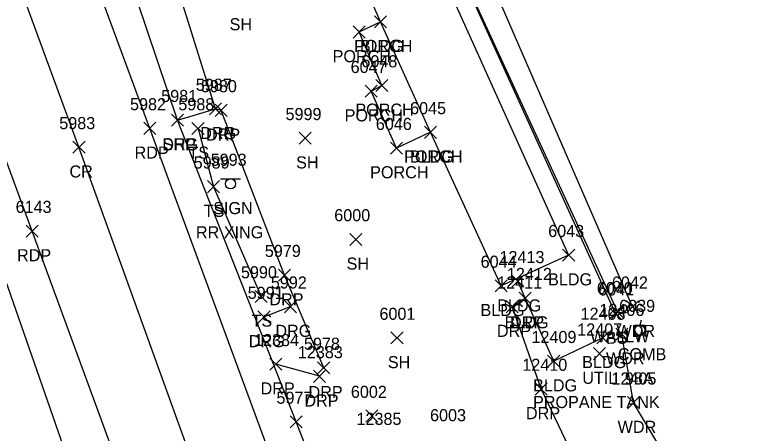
# Model space of a CAD drawing. Extents: x 1769141 to 1770817, y 735471 to 742405.
# Drawn here: x 1770316.5 to 1770439.6, y 740432.3 to 740501.5 of the extents above; entities that cross this region are included whole.
import ezdxf

# ---------------------------------------------------------------- set-up
doc = ezdxf.new("R2010")
doc.units = 0
for name, color, linetype in [('L_A', 7, 'Continuous'), ('L_I', 7, 'Continuous'), ('L_TIC', 7, 'Continuous'), ('LAWA', 7, 'Continuous'), ('LBC', 7, 'Continuous'), ('LBF', 7, 'Continuous'), ('LELB', 7, 'Continuous'), ('LW', 7, 'Continuous'), ('P_A', 7, 'Continuous'), ('P_I', 7, 'Continuous'), ('P_TIC', 7, 'Continuous'), ('PET', 7, 'Continuous'), ('PRC', 7, 'Continuous'), ('PSP', 7, 'Continuous'), ('R_A', 7, 'Continuous'), ('R_I', 7, 'Continuous'), ('R_TIC', 7, 'Continuous'), ('RDG', 7, 'Continuous'), ('RDP', 7, 'Continuous'), ('S_A', 7, 'Continuous'), ('S_C', 7, 'Continuous'), ('S_I', 7, 'Continuous'), ('SSGN', 7, 'Continuous'), ('U_A', 7, 'Continuous'), ('U_C', 7, 'Continuous'), ('U_I', 7, 'Continuous'), ('UDEFAULT', 7, 'Continuous'), ('UP', 7, 'Continuous')]:
    doc.layers.add(name, color=color, linetype=linetype)

msp = doc.modelspace()

# ---------------------------------------------------------------- linework, layer by layer
at = {"layer": 'L_TIC'}
for points in [[(1770375.95, 740499.35), (1770377.95, 740501.35)], [(1770377.95, 740499.35), (1770375.95, 740501.35)], [(1770375.95, 740499.35), (1770377.95, 740501.35)], [(1770377.95, 740499.35), (1770375.95, 740501.35)], [(1770372.41, 740497.66), (1770374.41, 740499.66)], [(1770374.41, 740497.66), (1770372.41, 740499.66)], [(1770376.17, 740488.81), (1770378.17, 740490.81)], [(1770378.17, 740488.81), (1770376.17, 740490.81)], [(1770374.4, 740487.87), (1770376.4, 740489.87)], [(1770376.4, 740487.87), (1770374.4, 740489.87)], [(1770345.76, 740481.7), (1770347.76, 740483.7)], [(1770347.76, 740481.7), (1770345.76, 740483.7)], [(1770384.24, 740481.06), (1770386.24, 740483.06)], [(1770386.24, 740481.06), (1770384.24, 740483.06)], [(1770384.24, 740481.06), (1770386.24, 740483.06)], [(1770386.24, 740481.06), (1770384.24, 740483.06)], [(1770363.5, 740480.08), (1770365.5, 740482.08)], [(1770365.5, 740480.08), (1770363.5, 740482.08)], [(1770378.62, 740478.45), (1770380.62, 740480.45)], [(1770380.62, 740478.45), (1770378.62, 740480.45)], [(1770348.3, 740472.06), (1770350.3, 740474.06)], [(1770350.3, 740472.06), (1770348.3, 740474.06)], [(1770371.86, 740463.34), (1770373.86, 740465.34)], [(1770373.86, 740463.34), (1770371.86, 740465.34)], [(1770407.08, 740460.73), (1770409.08, 740462.73)], [(1770409.08, 740460.73), (1770407.08, 740462.73)], [(1770398.67, 740456.41), (1770400.67, 740458.41)], [(1770400.67, 740456.41), (1770398.67, 740458.41)], [(1770395.91, 740455.65), (1770397.91, 740457.65)], [(1770397.91, 740455.65), (1770395.91, 740457.65)], [(1770356.21, 740453.9), (1770358.21, 740455.9)], [(1770358.21, 740453.9), (1770356.21, 740455.9)], [(1770399.9, 740453.62), (1770401.9, 740455.62)], [(1770401.9, 740453.62), (1770399.9, 740455.62)], [(1770415.23, 740451.28), (1770417.23, 740453.28)], [(1770417.23, 740451.28), (1770415.23, 740453.28)], [(1770417.64, 740452.2), (1770419.64, 740454.2)], [(1770419.64, 740452.2), (1770417.64, 740454.2)], [(1770414.81, 740451.06), (1770416.81, 740453.06)], [(1770416.81, 740451.06), (1770414.81, 740453.06)], [(1770415.89, 740447.67), (1770417.89, 740449.67)], [(1770417.89, 740447.67), (1770415.89, 740449.67)], [(1770378.68, 740447.03), (1770380.68, 740449.03)], [(1770380.68, 740447.03), (1770378.68, 740449.03)], [(1770412.73, 740447.04), (1770414.73, 740449.04)], [(1770414.73, 740447.04), (1770412.73, 740449.04)], [(1770404.61, 740443.19), (1770406.61, 740445.19)], [(1770406.61, 740443.19), (1770404.61, 740445.19)], [(1770417.83, 740436.32), (1770419.83, 740438.32)], [(1770419.83, 740436.32), (1770417.83, 740438.32)], [(1770374.52, 740434.12), (1770376.52, 740436.12)], [(1770376.52, 740434.12), (1770374.52, 740436.12)]]:
    msp.add_lwpolyline(points, dxfattribs=at)
at = {"layer": 'LAWA'}
for points in [[(1770418.64, 740453.2), (1770389.39, 740520.52), (1770361.77, 740519.09), (1770359.6, 740517.61), (1770360.27, 740535.74)], [(1770439.6, 740402.54), (1770418.83, 740437.32), (1770416.89, 740448.67)]]:
    msp.add_lwpolyline(points, dxfattribs=at)
at = {"layer": 'LBC'}
for points in [[(1770408.08, 740461.73), (1770396.91, 740456.65), (1770385.24, 740482.06), (1770376.95, 740500.35), (1770373.52, 740508.22), (1770384.84, 740513.28)], [(1770384.84, 740513.28), (1770408.08, 740461.73)], [(1770413.73, 740448.04), (1770405.61, 740444.19), (1770400.9, 740454.62), (1770399.67, 740457.41)]]:
    msp.add_lwpolyline(points, dxfattribs=at)
at = {"layer": 'LBF'}
msp.add_lwpolyline([(1770385.24, 740482.06), (1770379.62, 740479.45), (1770375.4, 740488.87), (1770377.17, 740489.81), (1770373.41, 740498.66), (1770376.95, 740500.35)], dxfattribs=at)
at = {"layer": 'LELB'}
for points in [[(1770415.81, 740452.06), (1770386.05, 740517.64), (1770374.61, 740517.07), (1770364.47, 740514.4), (1770359.6, 740517.61)], [(1770346.76, 740482.7), (1770349.3, 740473.06), (1770357.21, 740454.9)]]:
    msp.add_lwpolyline(points, dxfattribs=at)
at = {"layer": 'LW'}
msp.add_lwpolyline([(1770416.23, 740452.28), (1770385.94, 740518.08), (1770374.64, 740517.55)], dxfattribs=at)
at = {"layer": 'P_TIC'}
for points in [[(1770342.37, 740483.07), (1770344.37, 740485.07)], [(1770344.37, 740483.07), (1770342.37, 740485.07)], [(1770337.77, 740481.71), (1770339.77, 740483.71)], [(1770339.77, 740481.71), (1770337.77, 740483.71)], [(1770326.06, 740478.58), (1770328.06, 740480.58)], [(1770328.06, 740478.58), (1770326.06, 740480.58)], [(1770318.32, 740464.72), (1770320.32, 740466.72)], [(1770320.32, 740464.72), (1770318.32, 740466.72)], [(1770362, 740433.14), (1770364, 740435.14)], [(1770364, 740433.14), (1770362, 740435.14)]]:
    msp.add_lwpolyline(points, dxfattribs=at)
at = {"layer": 'PET'}
for points in [[(1770379.16, 740373.29), (1770360.22, 740424.51), (1770338.77, 740482.71), (1770320.68, 740531.7), (1770305.06, 740574.76), (1770283.59, 740632.55), (1770262.08, 740689.36), (1770241.57, 740741.19)], [(1770354.08, 740371.38), (1770337.26, 740416.85), (1770319.32, 740465.72), (1770304.6, 740505.64), (1770288.87, 740548.76), (1770274.11, 740588.9), (1770250.94, 740650.86), (1770225.28, 740717.64)]]:
    msp.add_lwpolyline(points, dxfattribs=at)
at = {"layer": 'PRC'}
msp.add_lwpolyline([(1770366.94, 740369.74), (1770348.35, 740420.63), (1770327.06, 740479.58), (1770309.33, 740527.72), (1770293.48, 740571.26), (1770272.53, 740627.61), (1770250.4, 740686.41), (1770230.69, 740735.91)], dxfattribs=at)
at = {"layer": 'PSP'}
for points in [[(1770384.34, 740374.74), (1770365.93, 740426.73), (1770363, 740434.14), (1770343.37, 740484.07), (1770326.57, 740533.85), (1770310.21, 740576.26), (1770285.85, 740639.32), (1770267.25, 740691.65), (1770245.28, 740742.42)], [(1770346.98, 740368.28), (1770329.75, 740414.99), (1770313.12, 740462.55), (1770298.15, 740502.39), (1770298.12, 740506.76), (1770283.52, 740546.61), (1770275.49, 740567.79), (1770273.86, 740568.65), (1770259.2, 740607.52), (1770260.25, 740609.6), (1770245.76, 740649.04), (1770220.84, 740715.43)]]:
    msp.add_lwpolyline(points, dxfattribs=at)
at = {"layer": 'R_TIC'}
for points in [[(1770348.64, 740484.93), (1770350.64, 740486.93)], [(1770350.64, 740484.93), (1770348.64, 740486.93)], [(1770348.64, 740484.93), (1770350.64, 740486.93)], [(1770350.64, 740484.93), (1770348.64, 740486.93)], [(1770349.59, 740484.69), (1770351.59, 740486.69)], [(1770351.59, 740484.69), (1770349.59, 740486.69)], [(1770342.37, 740483.07), (1770344.37, 740485.07)], [(1770344.37, 740483.07), (1770342.37, 740485.07)], [(1770360.07, 740457.43), (1770362.07, 740459.43)], [(1770362.07, 740457.43), (1770360.07, 740459.43)], [(1770399.9, 740453.62), (1770401.9, 740455.62)], [(1770401.9, 740453.62), (1770399.9, 740455.62)], [(1770361.07, 740452.21), (1770363.07, 740454.21)], [(1770363.07, 740452.21), (1770361.07, 740454.21)], [(1770397.73, 740452.21), (1770399.73, 740454.21)], [(1770399.73, 740452.21), (1770397.73, 740454.21)], [(1770356.67, 740450.5), (1770358.67, 740452.5)], [(1770358.67, 740450.5), (1770356.67, 740452.5)], [(1770358.62, 740442.68), (1770360.62, 740444.68)], [(1770360.62, 740442.68), (1770358.62, 740444.68)], [(1770366.55, 740442.07), (1770368.55, 740444.07)], [(1770368.55, 740442.07), (1770366.55, 740444.07)], [(1770365.87, 740440.68), (1770367.87, 740442.68)], [(1770367.87, 740440.68), (1770365.87, 740442.68)], [(1770402.53, 740438.59), (1770404.53, 740440.59)], [(1770404.53, 740438.59), (1770402.53, 740440.59)]]:
    msp.add_lwpolyline(points, dxfattribs=at)
at = {"layer": 'RDG'}
for points in [[(1770343.37, 740484.07), (1770349.64, 740485.93)], [(1770357.67, 740451.5), (1770362.07, 740453.21)]]:
    msp.add_lwpolyline(points, dxfattribs=at)
at = {"layer": 'RDP'}
for points in [[(1770367.55, 740443.07), (1770361.07, 740458.43), (1770350.59, 740485.69), (1770349.64, 740485.93), (1770339.16, 740519.48), (1770352.16, 740514.9), (1770373.02, 740508.09)], [(1770429.88, 740399.49), (1770425.49, 740409.67), (1770418.92, 740407.37), (1770403.53, 740439.59), (1770398.73, 740453.21), (1770400.9, 740454.62)], [(1770366.87, 740441.68), (1770359.62, 740443.68)]]:
    msp.add_lwpolyline(points, dxfattribs=at)
at = {"layer": 'SSGN'}
for p, q in [((1770350.48, 740474.38), (1770353.81, 740474.38)), ((1770352.13, 740473.54), (1770352.13, 740473.54))]:
    msp.add_line(p, q, dxfattribs=at)
msp.add_circle((1770352.13, 740473.54), 0.833, dxfattribs=at)
at = {"layer": 'UDEFAULT'}
for points in [[(1770412.18, 740444.43), (1770414.18, 740446.43)], [(1770414.18, 740444.43), (1770412.18, 740446.43)]]:
    msp.add_lwpolyline(points, dxfattribs=at)
at = {"layer": 'UP'}
for p, q in [((1770420.09, 740451), (1770419.84, 740450.17)), ((1770419, 740448.5), (1770419, 740450.17)), ((1770419, 740450.17), (1770420.67, 740450.17)), ((1770420.67, 740450.17), (1770420.67, 740448.5)), ((1770420.67, 740448.5), (1770419, 740448.5)), ((1770419.59, 740447.67), (1770419.84, 740448.5)), ((1770419.84, 740449.34), (1770419.84, 740449.34))]:
    msp.add_line(p, q, dxfattribs=at)
msp.add_circle((1770419.84, 740449.34), 0.833, dxfattribs=at)

# ---------------------------------------------------------------- texts
at = {"layer": 'L_A'}
for s, p in [('SH', (1770351.98, 740498.94)), ('PORCH', (1770372.57, 740495.35)), ('BLDG', (1770373.54, 740495.35)), ('PORCH', (1770369.03, 740493.66)), ('PORCH', (1770372.79, 740484.81)), ('PORCH', (1770371.02, 740483.87)), ('TS', (1770345.17, 740477.7)), ('SH', (1770362.99, 740476.08)), ('PORCH', (1770380.86, 740477.06)), ('BLDG', (1770381.83, 740477.06)), ('PORCH', (1770375.24, 740474.45)), ('TS', (1770347.71, 740468.06)), ('SH', (1770371.34, 740459.34)), ('BLDG', (1770404.68, 740456.73)), ('BLDG', (1770393.5, 740451.65)), ('BLDG', (1770396.26, 740452.41)), ('TS', (1770355.62, 740449.9)), ('BLDG', (1770397.49, 740449.62)), ('WDR', (1770416, 740448.2)), ('WALLW', (1770411.64, 740447.28)), ('BS', (1770414.25, 740447.06)), ('SH', (1770378.17, 740443.03)), ('BLDG', (1770410.32, 740443.04)), ('WDR', (1770414.26, 740443.67)), ('BLDG', (1770402.2, 740439.19)), ('WDR', (1770416.19, 740432.32))]:
    msp.add_text(s, height=2, dxfattribs=at).set_placement(p)
at = {"layer": 'L_I'}
for s, p in [('6047', (1770372.01, 740491.87)), ('6048', (1770373.79, 740492.81)), ('5988', (1770343.5, 740485.7)), ('6045', (1770381.85, 740485.06)), ('6045', (1770381.85, 740485.06)), ('5999', (1770361.24, 740484.08)), ('6046', (1770376.18, 740482.45)), ('5989', (1770346.04, 740476.06)), ('6000', (1770369.3, 740467.34)), ('6043', (1770404.7, 740464.73)), ('12413', (1770396.64, 740460.41)), ('6044', (1770393.52, 740459.65)), ('5990', (1770353.86, 740457.9)), ('12412', (1770397.87, 740457.62)), ('6042', (1770415.25, 740456.2)), ('6040', (1770412.75, 740455.28)), ('6041', (1770412.99, 740455.06)), ('12406', (1770413.17, 740451.67)), ('6001', (1770376.78, 740451.03)), ('12408', (1770410.06, 740451.04)), ('12409', (1770401.93, 740447.19)), ('12405', (1770415.16, 740440.32)), ('6002', (1770372.05, 740438.12)), ('6003', (1770385.15, 740434.25)), ('12385', (1770372.98, 740433.64))]:
    msp.add_text(s, height=2, dxfattribs=at).set_placement(p)
at = {"layer": 'P_A'}
for s, p in [('SHP', (1770340.9, 740479.07)), ('RDP', (1770336.26, 740477.71)), ('CR', (1770325.49, 740474.58)), ('RDP', (1770316.81, 740460.72))]:
    msp.add_text(s, height=2, dxfattribs=at).set_placement(p)
at = {"layer": 'P_I'}
for s, p in [('5981', (1770340.67, 740487.07)), ('5982', (1770335.51, 740485.71)), ('5983', (1770323.8, 740482.58)), ('6143', (1770316.58, 740468.72)), ('5977', (1770359.74, 740437.14))]:
    msp.add_text(s, height=2, dxfattribs=at).set_placement(p)
at = {"layer": 'R_A'}
for s, p in [('DRG', (1770347.13, 740480.93)), ('DRP', (1770347.13, 740480.93)), ('DRP', (1770348.08, 740480.69)), ('DRG', (1770340.85, 740479.07)), ('DRP', (1770358.56, 740453.43)), ('DRP', (1770398.38, 740449.62)), ('DRG', (1770359.56, 740448.21)), ('DRP', (1770396.22, 740448.21)), ('DRG', (1770355.16, 740446.5)), ('DRP', (1770357.11, 740438.68)), ('DRP', (1770365.04, 740438.07)), ('DRP', (1770364.36, 740436.68)), ('DRP', (1770401.02, 740434.59))]:
    msp.add_text(s, height=2, dxfattribs=at).set_placement(p)
at = {"layer": 'R_I'}
for s, p in [('5987', (1770346.38, 740488.93)), ('5987', (1770346.38, 740488.93)), ('5980', (1770347.24, 740488.69)), ('5981', (1770340.67, 740487.07)), ('5979', (1770357.81, 740461.43)), ('12412', (1770397.87, 740457.62)), ('5992', (1770358.81, 740456.21)), ('12411', (1770396.27, 740456.21)), ('5991', (1770354.98, 740454.5)), ('12384', (1770356.03, 740446.68)), ('5978', (1770364.29, 740446.07)), ('12383', (1770363.28, 740444.68)), ('12410', (1770400.42, 740442.59))]:
    msp.add_text(s, height=2, dxfattribs=at).set_placement(p)
at = {"layer": 'S_A'}
msp.add_text('SIGN', height=2, dxfattribs=at).set_placement((1770349.27, 740468.52))
at = {"layer": 'S_C'}
msp.add_text('RR XING', height=2, dxfattribs=at).set_placement((1770346.41, 740464.52))
at = {"layer": 'S_I'}
msp.add_text('5993', height=2, dxfattribs=at).set_placement((1770348.85, 740476.52))
at = {"layer": 'U_A'}
for s, p in [('COMB', (1770416.22, 740444.34)), ('UTIL', (1770410.34, 740440.43))]:
    msp.add_text(s, height=2, dxfattribs=at).set_placement(p)
at = {"layer": 'U_C'}
for s, p in [('98A', (1770417.39, 740440.34)), ('PROPANE TANK', (1770402.19, 740436.43))]:
    msp.add_text(s, height=2, dxfattribs=at).set_placement(p)
at = {"layer": 'U_I'}
for s, p in [('6039', (1770416.44, 740452.34)), ('12407', (1770409.51, 740448.43))]:
    msp.add_text(s, height=2, dxfattribs=at).set_placement(p)

doc.saveas('drawing.dxf')
